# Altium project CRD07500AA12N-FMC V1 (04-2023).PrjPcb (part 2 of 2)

## Sheet 05 - Sense.SchDoc: Sense - 7.5kW WolfPACK FM3 Six-Pack Motor Drive
size 431 x 279 mm; Date: 04/2023; DocumentNumber: CRD07500AA12N-FMC; Revision: 1; SheetNumber: 5; SheetTotal: 6; SheetSize: B
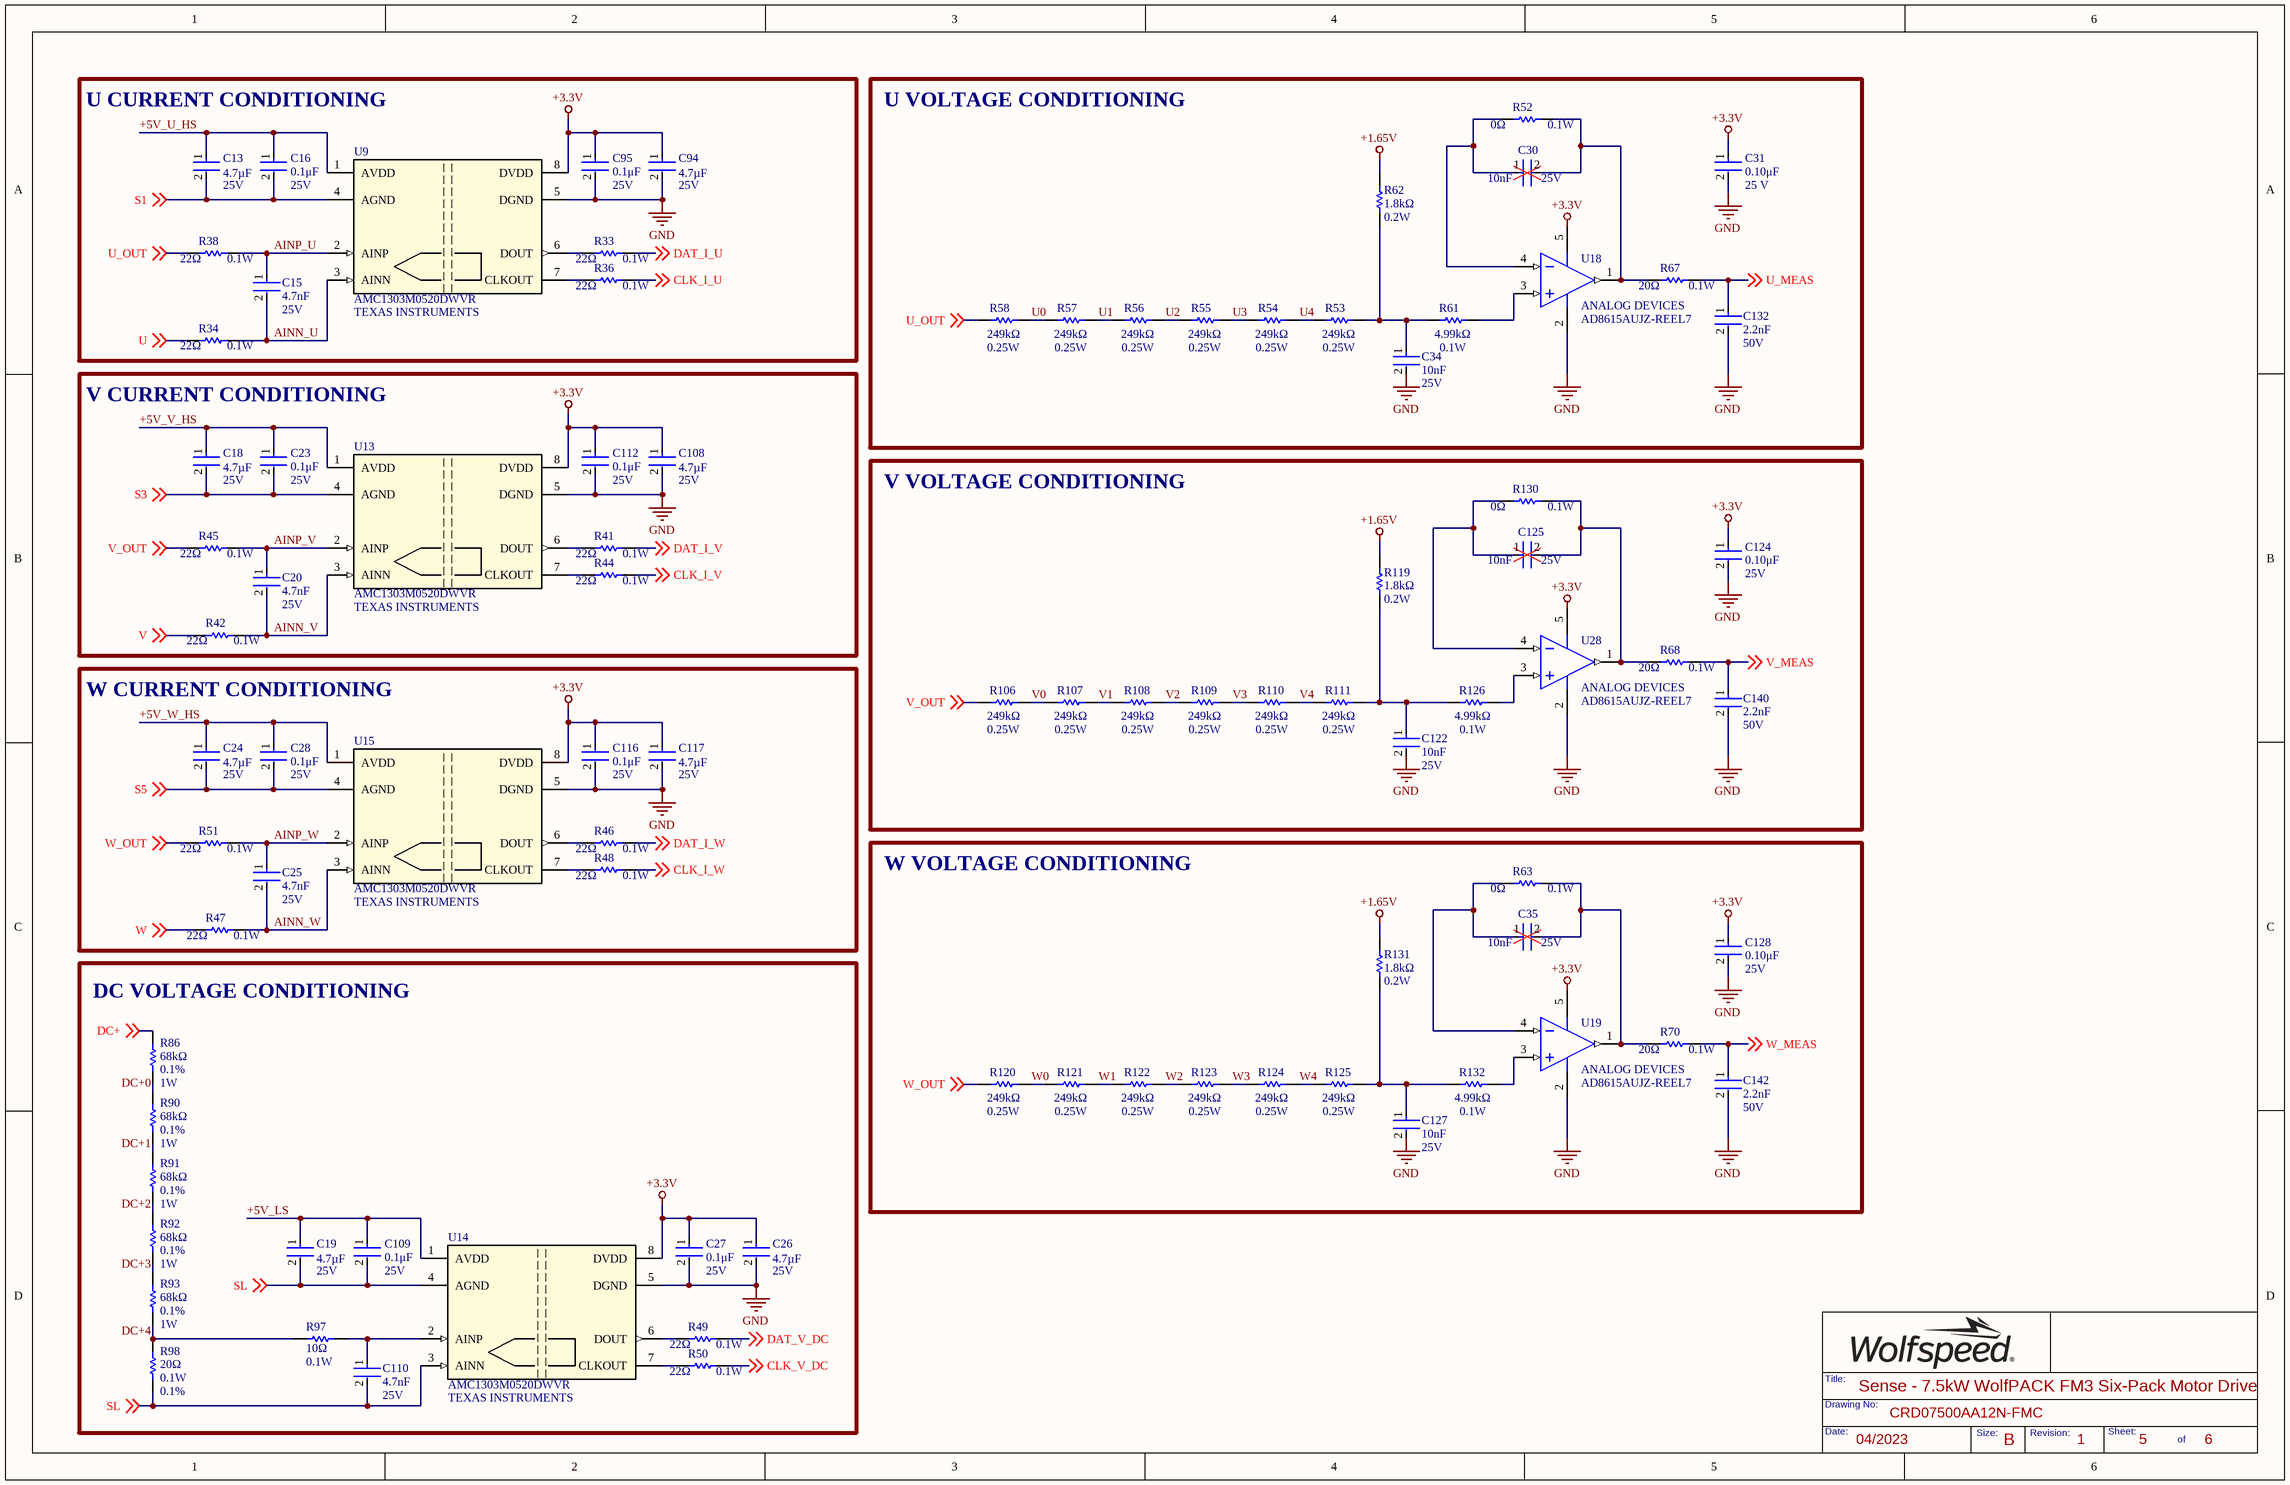
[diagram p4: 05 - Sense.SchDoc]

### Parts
C13  Capacitance: 4.7µF  Voltage Rating: 25V  [FP-C0603C-CF-IPC_B]  (hidden comment: CL10A475MA8NQNC)
C15  Capacitance: 4.7nF  Voltage Rating: 25V  [FP-C0603C-CF-IPC_B]  (hidden comment: C0603C472K3RAC7867)
C16  Voltage Rating: 25V  Capacitance: 0.1μF  [FP-C0603C-CF-IPC_B]  (hidden comment: C0603C104K3RACTU)
C18  Capacitance: 4.7µF  Voltage Rating: 25V  [FP-C0603C-CF-IPC_B]  (hidden comment: CL10A475MA8NQNC)
C19  Capacitance: 4.7µF  Voltage Rating: 25V  [FP-C0603C-CF-IPC_B]  (hidden comment: CL10A475MA8NQNC)
C20  Capacitance: 4.7nF  Voltage Rating: 25V  [FP-C0603C-CF-IPC_B]  (hidden comment: C0603C472K3RAC7867)
C23  Voltage Rating: 25V  Capacitance: 0.1μF  [FP-C0603C-CF-IPC_B]  (hidden comment: C0603C104K3RACTU)
C24  Capacitance: 4.7µF  Voltage Rating: 25V  [FP-C0603C-CF-IPC_B]  (hidden comment: CL10A475MA8NQNC)
C25  Capacitance: 4.7nF  Voltage Rating: 25V  [FP-C0603C-CF-IPC_B]  (hidden comment: C0603C472K3RAC7867)
C26  Capacitance: 4.7µF  Voltage Rating: 25V  [FP-C0603C-CF-IPC_B]  (hidden comment: CL10A475MA8NQNC)
C27  Voltage Rating: 25V  Capacitance: 0.1μF  [FP-C0603C-CF-IPC_B]  (hidden comment: C0603C104K3RACTU)
C28  Voltage Rating: 25V  Capacitance: 0.1μF  [FP-C0603C-CF-IPC_B]  (hidden comment: C0603C104K3RACTU)
C30  value 10nF  Voltage Rating: 25V  [FP-C0603C-CF-IPC_B]  (hidden comment: CL10B103KA8WPNC)
C31  Voltage Rating: 25 V  Capacitance: 0.10μF  [FP-C0603C-CF-IPC_B]  (hidden comment: C0603C104K3RACTU)
C34  value 10nF  Voltage Rating: 25V  [FP-C0603C-CF-IPC_B]  (hidden comment: CL10B103KA8WPNC)
C35  value 10nF  Voltage Rating: 25V  [FP-C0603C-CF-IPC_B]  (hidden comment: CL10B103KA8WPNC)
C94  Capacitance: 4.7µF  Voltage Rating: 25V  [FP-C0603C-CF-IPC_B]  (hidden comment: CL10A475MA8NQNC)
C95  Voltage Rating: 25V  Capacitance: 0.1μF  [FP-C0603C-CF-IPC_B]  (hidden comment: C0603C104K3RACTU)
C108  Capacitance: 4.7µF  Voltage Rating: 25V  [FP-C0603C-CF-IPC_B]  (hidden comment: CL10A475MA8NQNC)
C109  Voltage Rating: 25V  Capacitance: 0.1μF  [FP-C0603C-CF-IPC_B]  (hidden comment: C0603C104K3RACTU)
C110  Capacitance: 4.7nF  Voltage Rating: 25V  [FP-C0603C-CF-IPC_B]  (hidden comment: C0603C472K3RAC7867)
C112  Voltage Rating: 25V  Capacitance: 0.1μF  [FP-C0603C-CF-IPC_B]  (hidden comment: C0603C104K3RACTU)
C116  Voltage Rating: 25V  Capacitance: 0.1μF  [FP-C0603C-CF-IPC_B]  (hidden comment: C0603C104K3RACTU)
C117  Capacitance: 4.7µF  Voltage Rating: 25V  [FP-C0603C-CF-IPC_B]  (hidden comment: CL10A475MA8NQNC)
C122  value 10nF  Voltage Rating: 25V  [FP-C0603C-CF-IPC_B]  (hidden comment: CL10B103KA8WPNC)
C124  Voltage Rating: 25V  Capacitance: 0.10μF  [FP-C0603C-CF-IPC_B]  (hidden comment: C0603C104K3RACTU)
C125  value 10nF  Voltage Rating: 25V  [FP-C0603C-CF-IPC_B]  (hidden comment: CL10B103KA8WPNC)
C127  value 10nF  Voltage Rating: 25V  [FP-C0603C-CF-IPC_B]  (hidden comment: CL10B103KA8WPNC)
C128  Voltage Rating: 25V  Capacitance: 0.10μF  [FP-C0603C-CF-IPC_B]  (hidden comment: C0603C104K3RACTU)
C132  Capacitance: 2.2nF  Voltage Rating: 50V  [FP-GCM188-0_1-IPC_A]  (hidden comment: CGA3E2X7R1H222K080AA)
C140  Capacitance: 2.2nF  Voltage Rating: 50V  [FP-GCM188-0_1-IPC_A]  (hidden comment: CGA3E2X7R1H222K080AA)
C142  Capacitance: 2.2nF  Voltage Rating: 50V  [FP-GCM188-0_1-IPC_A]  (hidden comment: CGA3E2X7R1H222K080AA)
R33  Resistance: 22Ω  Power Rating: 0.1W  [FP-MCR03-IPC_B]  (hidden comment: RC0603FR-1322RL)
R34  Resistance: 22Ω  Power Rating: 0.1W  [FP-MCR03-IPC_B]  (hidden comment: RC0603FR-1322RL)
R36  Resistance: 22Ω  Power Rating: 0.1W  [FP-MCR03-IPC_B]  (hidden comment: RC0603FR-1322RL)
R38  Resistance: 22Ω  Power Rating: 0.1W  [FP-MCR03-IPC_B]  (hidden comment: RC0603FR-1322RL)
R41  Resistance: 22Ω  Power Rating: 0.1W  [FP-MCR03-IPC_B]  (hidden comment: RC0603FR-1322RL)
R42  Resistance: 22Ω  Power Rating: 0.1W  [FP-MCR03-IPC_B]  (hidden comment: RC0603FR-1322RL)
R44  Resistance: 22Ω  Power Rating: 0.1W  [FP-MCR03-IPC_B]  (hidden comment: RC0603FR-1322RL)
R45  Resistance: 22Ω  Power Rating: 0.1W  [FP-MCR03-IPC_B]  (hidden comment: RC0603FR-1322RL)
R46  Resistance: 22Ω  Power Rating: 0.1W  [FP-MCR03-IPC_B]  (hidden comment: RC0603FR-1322RL)
R47  Resistance: 22Ω  Power Rating: 0.1W  [FP-MCR03-IPC_B]  (hidden comment: RC0603FR-1322RL)
R48  Resistance: 22Ω  Power Rating: 0.1W  [FP-MCR03-IPC_B]  (hidden comment: RC0603FR-1322RL)
R49  Resistance: 22Ω  Power Rating: 0.1W  [FP-MCR03-IPC_B]  (hidden comment: RC0603FR-1322RL)
R50  Resistance: 22Ω  Power Rating: 0.1W  [FP-MCR03-IPC_B]  (hidden comment: RC0603FR-1322RL)
R51  Resistance: 22Ω  Power Rating: 0.1W  [FP-MCR03-IPC_B]  (hidden comment: RC0603FR-1322RL)
R52  Resistance: 0Ω  Power Rating: 0.1W  [FP-MCR03-IPC_B]  (hidden comment: RC0603FR-070RL)
R53  Resistance: 249kΩ  Power: 0.25W  [RESC3216X65X50NL15T25]  (hidden comment: TNPW1206249KBEEA)
R54  Resistance: 249kΩ  Power: 0.25W  [RESC3216X65X50NL15T25]  (hidden comment: TNPW1206249KBEEA)
R55  Resistance: 249kΩ  Power: 0.25W  [RESC3216X65X50NL15T25]  (hidden comment: TNPW1206249KBEEA)
R56  Resistance: 249kΩ  Power: 0.25W  [RESC3216X65X50NL15T25]  (hidden comment: TNPW1206249KBEEA)
R57  Resistance: 249kΩ  Power: 0.25W  [RESC3216X65X50NL15T25]  (hidden comment: TNPW1206249KBEEA)
R58  Resistance: 249kΩ  Power: 0.25W  [RESC3216X65X50NL15T25]  (hidden comment: TNPW1206249KBEEA)
R61  Power Rating: 0.1W  Resistance: 4.99kΩ  [FP-MCR03-IPC_B]  (hidden comment: RC0603FR-074K99L)
R62  Resistance: 1.8kΩ  Max Power Dissipation: 0.2W  [FP-MCR03-IPC_B]  (hidden comment: ERJ-PB3B1801V)
R63  Resistance: 0Ω  Power Rating: 0.1W  [FP-MCR03-IPC_B]  (hidden comment: RC0603FR-070RL)
R67  Resistance: 20Ω  Power Rating: 0.1W  [FP-MCR03-IPC_B]  (hidden comment: RT0603BRD0720RL)
R68  Resistance: 20Ω  Power Rating: 0.1W  [FP-MCR03-IPC_B]  (hidden comment: RT0603BRD0720RL)
R70  Resistance: 20Ω  Power Rating: 0.1W  [FP-MCR03-IPC_B]  (hidden comment: RT0603BRD0720RL)
R86  Resistance: 68kΩ  Power: 1W  Tolerance: 0.1%  [RESC3216X65X50NL15T25]  (hidden comment: PHPA1206E6802BST1)
R90  Resistance: 68kΩ  Power: 1W  Tolerance: 0.1%  [RESC3216X65X50NL15T25]  (hidden comment: PHPA1206E6802BST1)
R91  Resistance: 68kΩ  Power: 1W  Tolerance: 0.1%  [RESC3216X65X50NL15T25]  (hidden comment: PHPA1206E6802BST1)
R92  Resistance: 68kΩ  Power: 1W  Tolerance: 0.1%  [RESC3216X65X50NL15T25]  (hidden comment: PHPA1206E6802BST1)
R93  Resistance: 68kΩ  Power: 1W  Tolerance: 0.1%  [RESC3216X65X50NL15T25]  (hidden comment: PHPA1206E6802BST1)
R97  Resistance: 10Ω  Max Power Dissipation: 0.1W  [FP-MCR03-IPC_B]  (hidden comment: RC0603JR-0710RL)
R98  Tolerance: 0.1%  Resistance: 20Ω  Power Rating: 0.1W  [FP-MCR03-IPC_B]  (hidden comment: RT0603BRD0720RL)
R106  Resistance: 249kΩ  Power: 0.25W  [RESC3216X65X50NL15T25]  (hidden comment: TNPW1206249KBEEA)
R107  Resistance: 249kΩ  Power: 0.25W  [RESC3216X65X50NL15T25]  (hidden comment: TNPW1206249KBEEA)
R108  Resistance: 249kΩ  Power: 0.25W  [RESC3216X65X50NL15T25]  (hidden comment: TNPW1206249KBEEA)
R109  Resistance: 249kΩ  Power: 0.25W  [RESC3216X65X50NL15T25]  (hidden comment: TNPW1206249KBEEA)
R110  Resistance: 249kΩ  Power: 0.25W  [RESC3216X65X50NL15T25]  (hidden comment: TNPW1206249KBEEA)
R111  Resistance: 249kΩ  Power: 0.25W  [RESC3216X65X50NL15T25]  (hidden comment: TNPW1206249KBEEA)
R119  Resistance: 1.8kΩ  Max Power Dissipation: 0.2W  [FP-MCR03-IPC_B]  (hidden comment: ERJ-PB3B1801V)
R120  Resistance: 249kΩ  Power: 0.25W  [RESC3216X65X50NL15T25]  (hidden comment: TNPW1206249KBEEA)
R121  Resistance: 249kΩ  Power: 0.25W  [RESC3216X65X50NL15T25]  (hidden comment: TNPW1206249KBEEA)
R122  Resistance: 249kΩ  Power: 0.25W  [RESC3216X65X50NL15T25]  (hidden comment: TNPW1206249KBEEA)
R123  Resistance: 249kΩ  Power: 0.25W  [RESC3216X65X50NL15T25]  (hidden comment: TNPW1206249KBEEA)
R124  Resistance: 249kΩ  Power: 0.25W  [RESC3216X65X50NL15T25]  (hidden comment: TNPW1206249KBEEA)
R125  Resistance: 249kΩ  Power: 0.25W  [RESC3216X65X50NL15T25]  (hidden comment: TNPW1206249KBEEA)
R126  Power Rating: 0.1W  Resistance: 4.99kΩ  [FP-MCR03-IPC_B]  (hidden comment: RC0603FR-074K99L)
R130  Resistance: 0Ω  Power Rating: 0.1W  [FP-MCR03-IPC_B]  (hidden comment: RC0603FR-070RL)
R131  Resistance: 1.8kΩ  Max Power Dissipation: 0.2W  [FP-MCR03-IPC_B]  (hidden comment: ERJ-PB3B1801V)
R132  Power Rating: 0.1W  Resistance: 4.99kΩ  [FP-MCR03-IPC_B]  (hidden comment: RC0603FR-074K99L)
U9  AMC1303M0520DWVR  Manufacturer: TEXAS INSTRUMENTS  [DWV0008A]
U13  AMC1303M0520DWVR  Manufacturer: TEXAS INSTRUMENTS  [DWV0008A]
U14  AMC1303M0520DWVR  Manufacturer: TEXAS INSTRUMENTS  [DWV0008A]
U15  AMC1303M0520DWVR  Manufacturer: TEXAS INSTRUMENTS  [DWV0008A]
U18  Manufacturer: ANALOG DEVICES  [ADI-UJ-5_M]  (hidden comment: AD8615AUJZ-REEL7)
U19  Manufacturer: ANALOG DEVICES  [ADI-UJ-5_M]  (hidden comment: AD8615AUJZ-REEL7)
U28  Manufacturer: ANALOG DEVICES  [ADI-UJ-5_M]  (hidden comment: AD8615AUJZ-REEL7)

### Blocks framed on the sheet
U CURRENT CONDITIONING: C13 C15 C16 C94 C95 R33 R34 R36 R38 U9
U VOLTAGE CONDITIONING: C30 C31 C34 C132 R52-R58 R61 R62 R67 U18
V CURRENT CONDITIONING: C18 C20 C23 C108 C112 R41 R42 R44 R45 U13
V VOLTAGE CONDITIONING: C122 C124 C125 C140 R68 R106-R111 R119 R126 R130 U28
W CURRENT CONDITIONING: C24 C25 C28 C116 C117 R46-R48 R51 U15
W VOLTAGE CONDITIONING: C35 C127 C128 C142 R63 R70 R120-R125 R131 R132 U19
DC VOLTAGE CONDITIONING: C19 C26 C27 C109 C110 R49 R50 R86 R90-R93 R97 R98 U14

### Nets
+1.65V: R62.2 R119.2 R131.2
+3.3V: C26.1 C27.1 C31.1 C94.1 C95.1 C108.1 C112.1 C116.1 C117.1 C124.1 C128.1 U9.8(DVDD) U13.8(DVDD) U14.8(DVDD) U15.8(DVDD) U18.5(+V) U19.5(+V) U28.5(+V)
GND: C26.2 C27.2 C31.2 C34.2 C94.2 C95.2 C108.2 C112.2 C116.2 C117.2 C122.2 C124.2 C127.2 C128.2 C132.2 C140.2 C142.2 U9.5(DGND) U13.5(DGND) U14.5(DGND) U15.5(DGND) U18.2(-V) U19.2(-V) U28.2(-V)
+5V_LS: C19.1 C109.1 U14.1(AVDD)
+5V_U_HS: C13.1 C16.1 U9.1(AVDD)
+5V_V_HS: C18.1 C23.1 U13.1(AVDD)
+5V_W_HS: C24.1 C28.1 U15.1(AVDD)
AINN_U: C15.2 R34.2 U9.3(AINN)
AINN_V: C20.2 R42.2 U13.3(AINN)
AINN_W: C25.2 R47.2 U15.3(AINN)
AINP_U: C15.1 R38.2 U9.2(AINP)
AINP_V: C20.1 R45.2 U13.2(AINP)
AINP_W: C25.1 R51.2 U15.2(AINP)
CLK_I_U: R36.2 ; off-sheet CLK_I_U
CLK_I_V: R44.2 ; off-sheet CLK_I_V
CLK_I_W: R48.2 ; off-sheet CLK_I_W
CLK_V_DC: R50.2 ; off-sheet CLK_V_DC
DAT_I_U: R33.2 ; off-sheet DAT_I_U
DAT_I_V: R41.2 ; off-sheet DAT_I_V
DAT_I_W: R46.2 ; off-sheet DAT_I_W
DAT_V_DC: R49.2 ; off-sheet DAT_V_DC
DC+: R86.2 ; off-sheet DC+
DC+0: R86.1 R90.2
DC+1: R90.1 R91.2
DC+2: R91.1 R92.2
DC+3: R92.1 R93.2
DC+4: R93.1 R97.2 R98.2
S1: C13.2 C16.2 U9.4(AGND) ; off-sheet S1
S3: C18.2 C23.2 U13.4(AGND) ; off-sheet S3
S5: C24.2 C28.2 U15.4(AGND) ; off-sheet S5
SL: C19.2 C109.2 C110.2 R98.1 U14.3(AINN) U14.4(AGND) ; off-sheet SL
U: R34.1 ; off-sheet U
U0: R57.1 R58.2
U1: R56.1 R57.2
U2: R55.1 R56.2
U3: R54.1 R55.2
U4: R53.1 R54.2
U_MEAS: C132.1 R67.2 ; off-sheet U_MEAS
U_OUT: R38.1 R58.1 ; off-sheet U_OUT
V: R42.1 ; off-sheet V
V0: R106.2 R107.1
V1: R107.2 R108.1
V2: R108.2 R109.1
V3: R109.2 R110.1
V4: R110.2 R111.1
V_MEAS: C140.1 R68.2 ; off-sheet V_MEAS
V_OUT: R45.1 R106.1 ; off-sheet V_OUT
W: R47.1 ; off-sheet W
W0: R120.2 R121.1
W1: R121.2 R122.1
W2: R122.2 R123.1
W3: R123.2 R124.1
W4: R124.2 R125.1
W_MEAS: C142.1 R70.2 ; off-sheet W_MEAS
W_OUT: R51.1 R120.1 ; off-sheet W_OUT
NetC30_1: C30.1 R52.2 U18.4(-IN)
NetC30_2: C30.2 R52.1 R67.1 U18.1(OUT)
NetC34_1: C34.1 R53.2 R61.1 R62.1
NetC35_1: C35.1 R63.2 U19.4(-IN)
NetC35_2: C35.2 R63.1 R70.1 U19.1(OUT)
NetC110_1: C110.1 R97.1 U14.2(AINP)
NetC122_1: C122.1 R111.2 R119.1 R126.1
NetC125_1: C125.1 R130.2 U28.4(-IN)
NetC125_2: C125.2 R68.1 R130.1 U28.1(OUT)
NetC127_1: C127.1 R125.2 R131.1 R132.1
NetR33_1: R33.1 U9.6(DOUT)
NetR36_1: R36.1 U9.7(CLKOUT)
NetR41_1: R41.1 U13.6(DOUT)
NetR44_1: R44.1 U13.7(CLKOUT)
NetR46_1: R46.1 U15.6(DOUT)
NetR48_1: R48.1 U15.7(CLKOUT)
NetR49_1: R49.1 U14.6(DOUT)
NetR50_1: R50.1 U14.7(CLKOUT)
NetR61_2: R61.2 U18.3(+IN)
NetR126_2: R126.2 U28.3(+IN)
NetR132_2: R132.2 U19.3(+IN)

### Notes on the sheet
- Labels drawn without touching a wire or pin: ~{}

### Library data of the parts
C13 C18 C19 C24 C26 C94 C108 C117 = CL10A475MA8NQNC: CAP CER 4.7UF 25V X5R 0603; Manufacturer: SAMSUNG; Tolerance: 20%; Value: 4.7µF
C15 C20 C25 C110 = C0603C472K3RAC7867: CAP CER 4700PF 25V 10% X7R 0603; Manufacturer: KEMET; Manufacturer Part Number: C0603C472K3RACTU; Dielectric Material: Ceramic; Value: 4.7nF
C16 C23 C27 C28 C31 C95 C109 C112 C116 C124 C128 = CMP-2006-03057-2: CAP CER 0.1UF 25V X7R 0603; Manufacturer: KEMET; Value: 0.10μF; Material: Ceramic; Tolerance: 0.1; Temperature Coefficient: 30ppm/°C; Automotive Grade: Grade 1
C30 C34 C35 C122 C125 C127 = CL10B103KA8WPNC: CAP CER 10000PF 25V X7R 0603; Manufacturer: SAMSUNG; Tolerance: 10%
C132 C140 C142 = CGA3E2X7R1H222K080AA: CAP CER 2200PF 50V X7R 0603; Manufacturer: TDK; Tolerance: 10%; Value: 2.2nF
R33 R34 R36 R38 R41 R42 R44-R51 = RC0603FR-1322RL: RES 22 OHM 1% 1/10W 0603; Manufacturer: YAGEO; Temperature Coefficient: 100ppm/°C; Voltage Rating: 50V; Value: 22Ω
R52 R63 R130 = RC0603FR-070RL: RES 0 OHM JUMPER 1/10W 0603; Manufacturer: YAGEO; Tolerance: 1%; Voltage Rating (DC): 50V; Max Power Dissipation: 100mW; Temperature Coefficient: 200ppm/°C; Current Rating: 1A; Working Voltage: 75V; Value: 0Ω
R53 R111 R125 = CMP-2003-04604-1: RES 249K OHM 0.1% 1/4W 1206; Manufacturer: VISHAY DALE; Value: 249kΩ
R54-R58 R106-R110 R120-R124 = CMP-2003-04604-1: RES 249K OHM 0.1% 1/4W 1206; Manufacturer: VISHAY; Value: 249kΩ
R61 R126 R132 = RC0603FR-074K99L: RES 4.99K OHM 1% 1/10W 0603; Manufacturer: YAGEO; Voltage Rating: 75V; Temperature Coefficient: 100ppm/°C; Voltage Rating (DC): 50V; Value: 4.99kΩ
R62 R119 R131 = ERJ-PB3B1801V: RES SMD 1.8K OHM 0.1% 1/5W 0603; Manufacturer: PANASONIC; Temperature Coefficient: 50ppm/°C; Value: 1.8kΩ
R67 R68 R70 R98 = RT0603BRD0720RL: RES SMD 20 OHM 0.1% 1/10W 0603; Manufacturer: YAGEO; Temperature Coefficient: 25ppm/°C; Max Power Dissipation: 100mW; Voltage Rating: 75V; Voltage Rating (DC): 50V; Value: 20Ω
R86 R90-R93 = PHPA1206E6802BST1: THIN FILM RES SMD 68K OHM 0.1% 1; Manufacturer: VISHAY; Value: 68kΩ
R97 = RC0603JR-0710RL: RES 10 OHM 5% 1/10W 0603; Manufacturer: YAGEO; Temperature Coefficient: 200ppm/°C; Power Rating: 100mW; Voltage Rating: 50V; Value: 10Ω
U9 U13-U15 = AMC1303M0520DWVR: IC ISOLATED MOD 16BIT 78K 8SOIC; Interface: Serial; Number of Inputs: 1
U18 U19 U28 = CMP-0384-02059-2: IC OPAMP GP 1 CIRCUIT TSOT23-5; Generic Part Number: AD8615; Iq/Amp: 1.7mA; V Span Max: 6V; Amplifiers Per Package: 1; Small Signal Bandwidth: 23MHz; Input Offset Voltage: 80uV; V Span Min: 2.7V; Slew Rate: 12V/us; Input Bias Current: 200fA

## Sheet 06 - Auxiliary Power.SchDoc: Auxiliary Power - 7.5kW WolfPACK 6-Pack M. Drive
size 431 x 279 mm; Date: 04/2023; DocumentNumber: CRD07500AA12N-FMC; Revision: 1; SheetNumber: 6; SheetTotal: 6; SheetSize: B
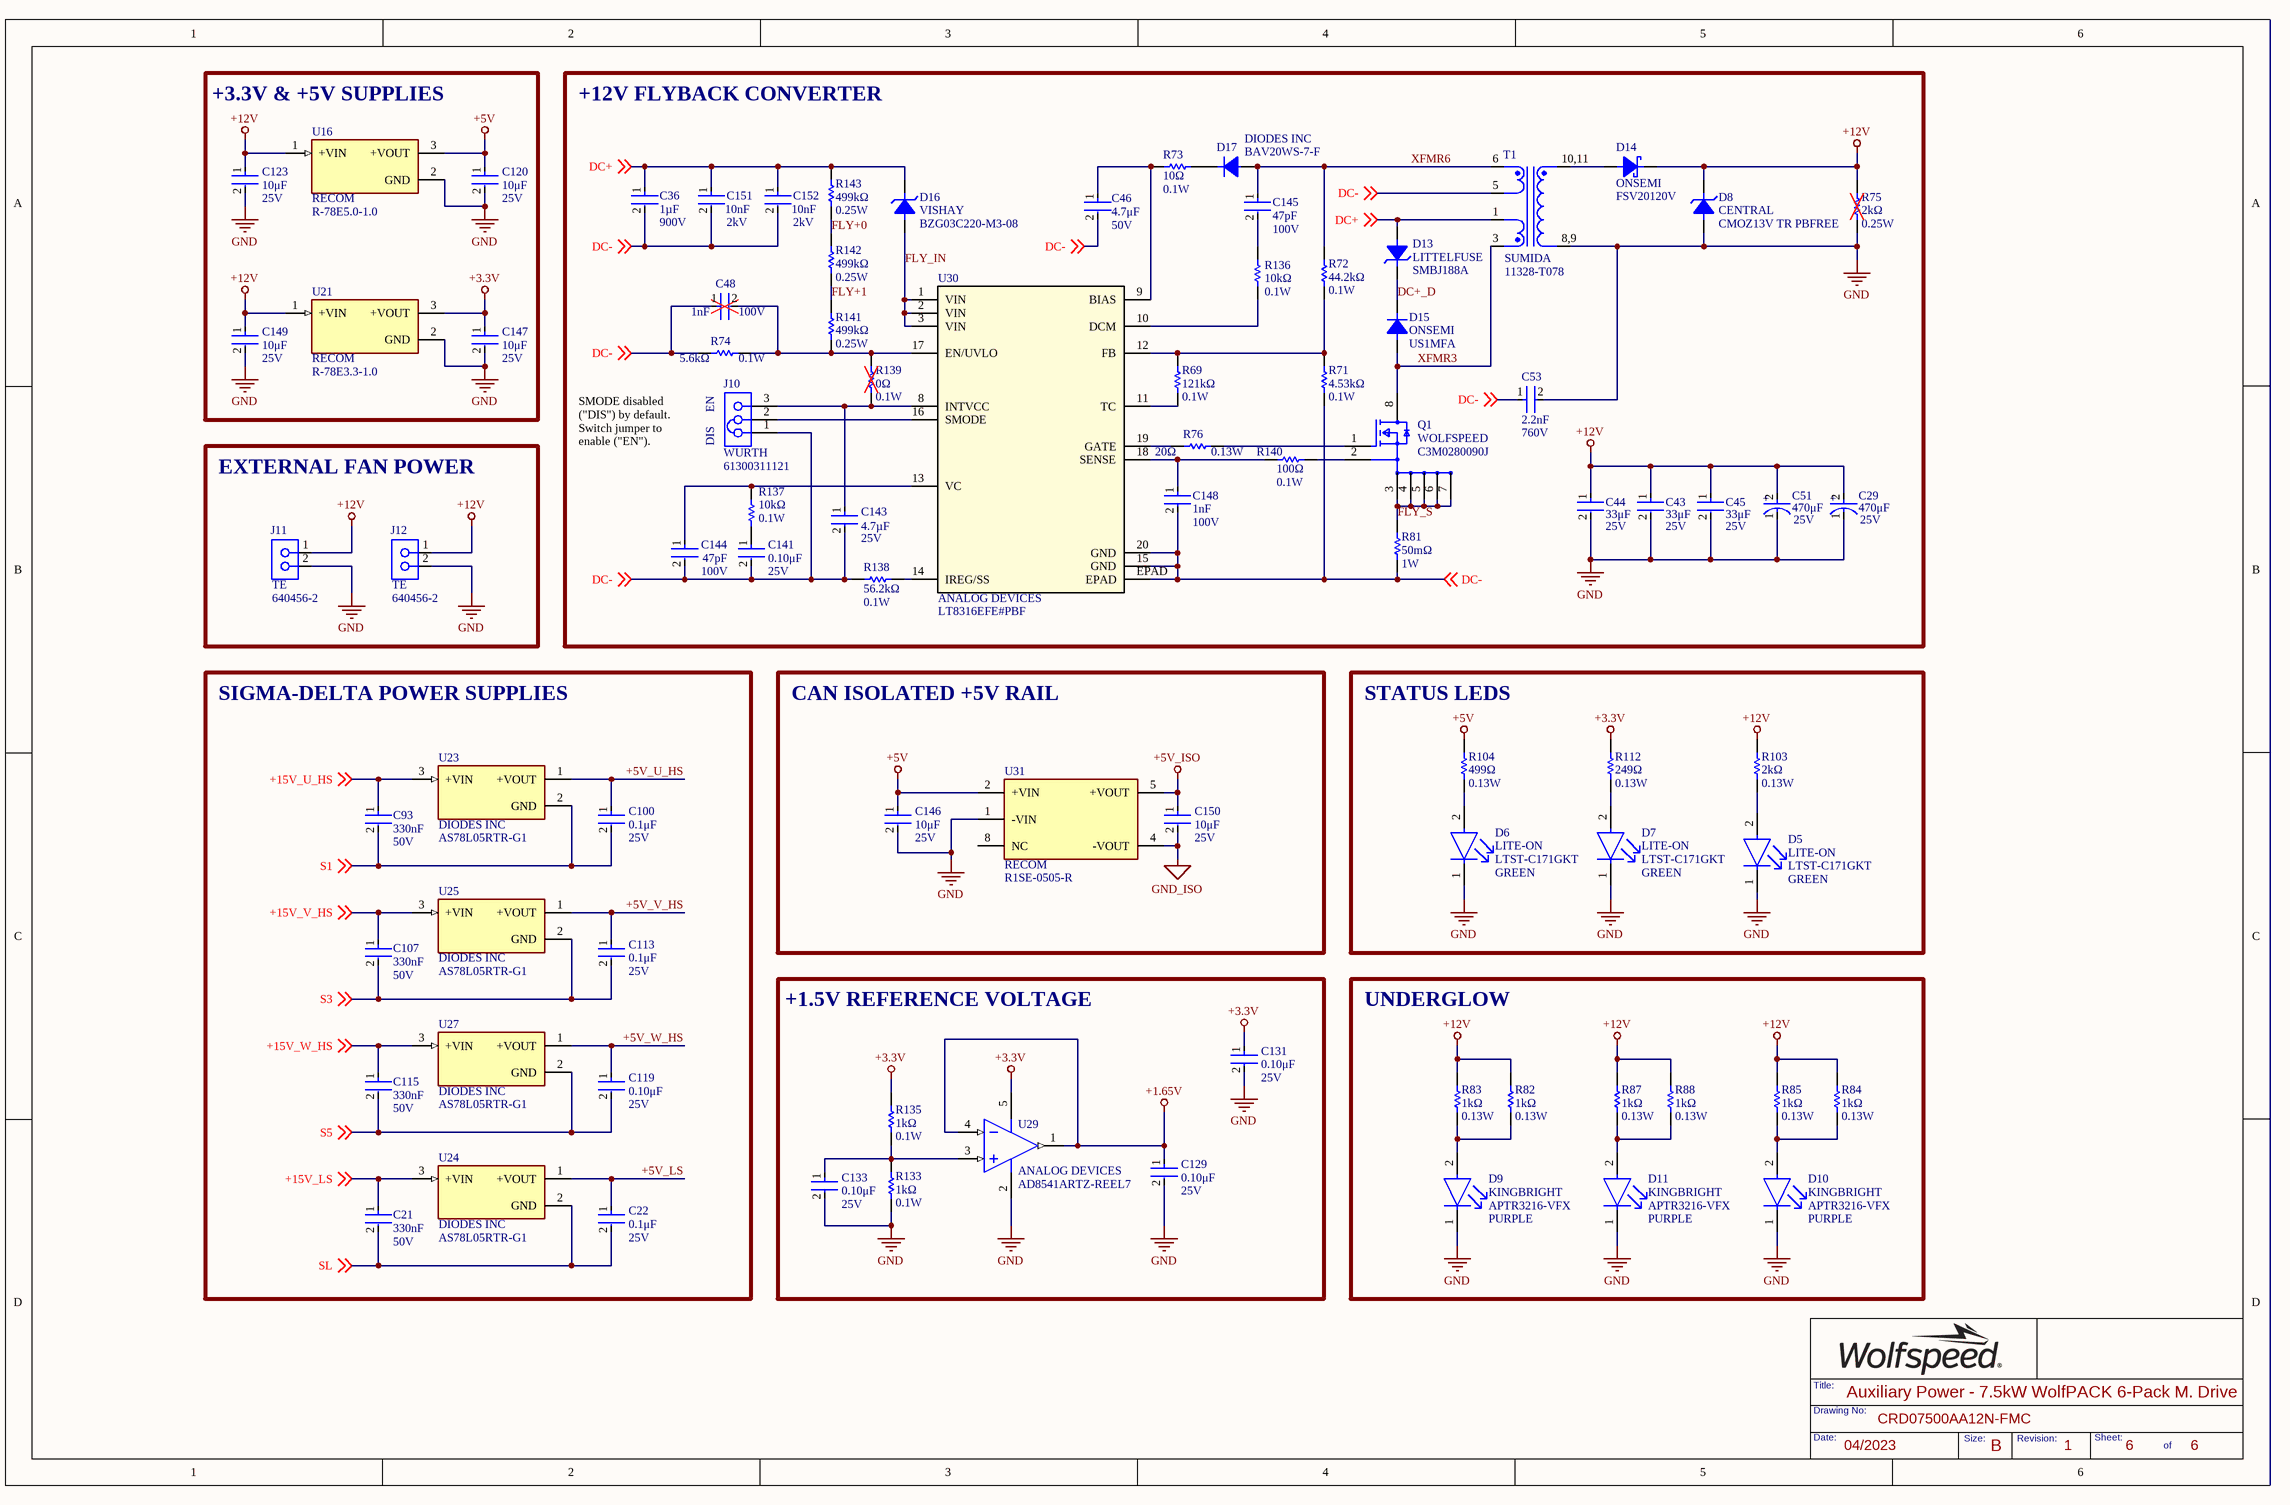
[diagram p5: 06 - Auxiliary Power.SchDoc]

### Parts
C21  Capacitance: 330nF  Voltage: 50V  [FP-C0603C-CF-IPC_B]  (hidden comment: C1608X7R1H334K080AC)
C22  Voltage Rating: 25V  Capacitance: 0.1μF  [FP-C0603C-CF-IPC_B]  (hidden comment: C0603C104K3RACTU)
C29  Voltage Rating: 25V  Capacitance: 470μF  [FP-EEH-G-MFG]  (hidden comment: EEHZK1E471P)
C36  Capacitance: 1µF  Rated Voltage (DC): 900V  [WCAP-FTDB_L32W9H18]  (hidden comment: 890724427001CS)
C43  Voltage Rating (DC): 25V  Capacitance: 33μF  [FP-C3216-160-0_2-IPC_C]  (hidden comment: C3216JB1E336M160AC)
C44  Voltage Rating (DC): 25V  Capacitance: 33μF  [FP-C3216-160-0_2-IPC_C]  (hidden comment: C3216JB1E336M160AC)
C45  Voltage Rating (DC): 25V  Capacitance: 33μF  [FP-C3216-160-0_2-IPC_C]  (hidden comment: C3216JB1E336M160AC)
C46  Voltage Rating: 50V  Capacitance: 4.7μF  [FP-CL21-IPC_C]  (hidden comment: CL21A475KBQNNNE)
C48  Capacitance: 1nF  Voltage Rating: 100V  [FP-C0603C-CF-IPC_B]  (hidden comment: C0603C102J1GACTU)
C51  Voltage Rating: 25V  Capacitance: 470μF  [FP-EEH-G-MFG]  (hidden comment: EEHZK1E471P)
C53  Capacitance: 2.2nF  Voltage Rating (AC): 760V  [FP-VY1470-MFG]  (hidden comment: VY1222M47Y5UQ6TV0)
C93  Capacitance: 330nF  Voltage: 50V  [FP-C0603C-CF-IPC_B]  (hidden comment: C1608X7R1H334K080AC)
C100  Voltage Rating: 25V  Capacitance: 0.1μF  [FP-C0603C-CF-IPC_B]  (hidden comment: C0603C104K3RACTU)
C107  Capacitance: 330nF  Voltage: 50V  [FP-C0603C-CF-IPC_B]  (hidden comment: C1608X7R1H334K080AC)
C113  Voltage Rating: 25V  Capacitance: 0.1μF  [FP-C0603C-CF-IPC_B]  (hidden comment: C0603C104K3RACTU)
C115  Capacitance: 330nF  Voltage: 50V  [FP-C0603C-CF-IPC_B]  (hidden comment: C1608X7R1H334K080AC)
C119  Voltage Rating: 25V  Capacitance: 0.10μF  [FP-C0603C-CF-IPC_B]  (hidden comment: C0603C104K3RACTU)
C120  Voltage Rating: 25V  Capacitance: 10μF  [FP-CL31-IPC_B]  (hidden comment: CL31B106KAHSFNE)
C123  Voltage Rating: 25V  Capacitance: 10μF  [FP-CL31-IPC_B]  (hidden comment: CL31B106KAHSFNE)
C129  Voltage Rating: 25V  Capacitance: 0.10μF  [FP-C0603C-CF-IPC_B]  (hidden comment: C0603C104K3RACTU)
C131  Voltage Rating: 25V  Capacitance: 0.10μF  [FP-C0603C-CF-IPC_B]  (hidden comment: C0603C104K3RACTU)
C133  Voltage Rating: 25V  Capacitance: 0.10μF  [FP-C0603C-CF-IPC_B]  (hidden comment: C0603C104K3RACTU)
C141  Voltage Rating: 25V  Capacitance: 0.10μF  [FP-C0603C-CF-IPC_B]  (hidden comment: C0603C104K3RACTU)
C143  Capacitance: 4.7µF  Voltage Rating: 25V  [FP-C0603C-CF-IPC_B]  (hidden comment: CL10A475MA8NQNC)
C144  Capacitance: 47pF  Voltage Rating: 100V  [FP-C0603C-CF-MFG]  (hidden comment: C0603C470K1GACTU)
C145  Capacitance: 47pF  Voltage Rating: 100V  [FP-C0603C-CF-MFG]  (hidden comment: C0603C470K1GACTU)
C146  Voltage Rating: 25V  Capacitance: 10μF  [FP-CL31-IPC_B]  (hidden comment: CL31B106KAHSFNE)
C147  Voltage Rating: 25V  Capacitance: 10μF  [FP-CL31-IPC_B]  (hidden comment: CL31B106KAHSFNE)
C148  Capacitance: 1nF  Voltage Rating: 100V  [FP-C0603C-CF-IPC_B]  (hidden comment: C0603C102J1GACTU)
C149  Voltage Rating: 25V  Capacitance: 10μF  [FP-CL31-IPC_B]  (hidden comment: CL31B106KAHSFNE)
C150  Voltage Rating: 25V  Capacitance: 10μF  [FP-CL31-IPC_B]  (hidden comment: CL31B106KAHSFNE)
C151  Voltage Rating: 2kV  Capacitance: 10nF  [FP-C5750-250-0_4-IPC_A]  (hidden comment: C5750X7S3D103K250KA)
C152  Voltage Rating: 2kV  Capacitance: 10nF  [FP-C5750-250-0_4-IPC_A]  (hidden comment: C5750X7S3D103K250KA)
D5  value GREEN  Manufacturer: LITE-ON  [FP-LTST-C171GKT-MFG]  (hidden comment: LTST-C171GKT)
D6  value GREEN  Manufacturer: LITE-ON  [FP-LTST-C171GKT-MFG]  (hidden comment: LTST-C171GKT)
D7  value GREEN  Manufacturer: LITE-ON  [FP-LTST-C171GKT-MFG]  (hidden comment: LTST-C171GKT)
D8  Manufacturer: CENTRAL  [DIODE_SOD-523_1P2XP8_CNS]  (hidden comment: CMOZ13V TR PBFREE)
D9  Manufacturer Print: KINGBRIGHT  Color: PURPLE  [FP-APTR3216SECK-MFG]  (hidden comment: APTR3216-VFX)
D10  Manufacturer Print: KINGBRIGHT  Color: PURPLE  [FP-APTR3216SECK-MFG]  (hidden comment: APTR3216-VFX)
D11  Manufacturer Print: KINGBRIGHT  Color: PURPLE  [FP-APTR3216SECK-MFG]  (hidden comment: APTR3216-VFX)
D13  Manufacturer: LITTELFUSE  [SMBJSeries_LTF]  (hidden comment: SMBJ188A)
D14  Manufacturer: ONSEMI  [SOT_20100V_ONS]  (hidden comment: FSV20120V)
D15  Manufacturer: ONSEMI  [FP-425AB-MFG]  (hidden comment: US1MFA)
D16  Manufacturer: VISHAY  [FP-SMA-MFG]  (hidden comment: BZG03C220-M3-08)
D17  Manufacturer: DIODES INC  [SOD323_DIO]  (hidden comment: BAV20WS-7-F)
J10  Manufacturer: WURTH  [61300311121]  (hidden comment: 61300311121)
J11  640456-2  Manufacturer Print: TE  [TECO-640456-2_V]
J12  640456-2  Manufacturer Print: TE  [TECO-640456-2_V]
Q1  Manufacturer: WOLFSPEED  [FP-TO-263-7-MFG]  (hidden comment: C3M0280090J)
R69  Resistance: 121kΩ  Power Rating: 0.1W  [FP-MCR03-IPC_B]  (hidden comment: RT0603FRE07121KL)
R71  Resistance: 4.53kΩ  Power Rating: 0.1W  [FP-MCR03-IPC_B]  (hidden comment: RC0603FR-074K53L)
R72  Resistance: 44.2kΩ  Max Power Dissipation: 0.1W  [FP-MCR03-IPC_B]  (hidden comment: RT0603BRD0744K2L)
R73  Resistance: 10Ω  Max Power Dissipation: 0.1W  [FP-MCR03-IPC_B]  (hidden comment: RC0603JR-0710RL)
R74  Resistance: 5.6kΩ  Power Rating: 0.1W  [FP-MCR03-IPC_B]  (hidden comment: RC0603FR-135K6L)
R75  Resistance: 2kΩ  Max Power Dissipation: 0.25W  [FP-CSR1206-IPC_A]  (hidden comment: RT1206FRE072KL)
R76  Resistance: 20Ω  Max Power Dissipation: 0.13W  [RESC2013X60X35LL10T20]  (hidden comment: RT0805FRE0720RL)
R81  value 50mΩ  Power: 1W  [FP-CSR1206-IPC_A]  (hidden comment: WFC1206R0500FE66)
R82  Resistance: 1kΩ  Power Rating: 0.13W  [RESC2013X50X30LL20T20]  (hidden comment: CRCW08051K00JNTA)
R83  Resistance: 1kΩ  Power Rating: 0.13W  [RESC2013X50X30LL20T20]  (hidden comment: CRCW08051K00JNTA)
R84  Resistance: 1kΩ  Power Rating: 0.13W  [RESC2013X50X30LL20T20]  (hidden comment: CRCW08051K00JNTA)
R85  Resistance: 1kΩ  Power Rating: 0.13W  [RESC2013X50X30LL20T20]  (hidden comment: CRCW08051K00JNTA)
R87  Resistance: 1kΩ  Power Rating: 0.13W  [RESC2013X50X30LL20T20]  (hidden comment: CRCW08051K00JNTA)
R88  Resistance: 1kΩ  Power Rating: 0.13W  [RESC2013X50X30LL20T20]  (hidden comment: CRCW08051K00JNTA)
R103  Resistance: 2kΩ  Max Power Dissipation: 0.13W  [FP-MCR10-IPC_A]  (hidden comment: RT0805FRE072KL)
R104  Resistance: 499Ω  Max Power Dissipation: 0.13W  [FP-MCR10-IPC_A]  (hidden comment: RC0805FR-07499RL)
R112  Resistance: 249Ω  Power Rating: 0.13W  [FP-MCR10-IPC_A]  (hidden comment: RC0805FR-07249RL)
R133  Resistance: 1kΩ  Power Rating: 0.1W  [FP-MCR03-IPC_B]  (hidden comment: RT0603DRD071KL)
R135  Resistance: 1kΩ  Power Rating: 0.1W  [FP-MCR03-IPC_B]  (hidden comment: RT0603DRD071KL)
R136  Resistance: 10kΩ  Max Power Dissipation: 0.1W  [FP-MCR03-IPC_B]  (hidden comment: ERJ3EKF1002V)
R137  Resistance: 10kΩ  Max Power Dissipation: 0.1W  [FP-MCR03-IPC_B]  (hidden comment: ERJ3EKF1002V)
R138  Resistance: 56.2kΩ  Power Rating: 0.1W  [FP-MCR03-IPC_B]  (hidden comment: RT0603BRD0756K2L)
R139  Resistance: 0Ω  Power Rating: 0.1W  [FP-MCR03-IPC_B]  (hidden comment: RC0603FR-070RL)
R140  Resistance: 100Ω  Power Rating: 0.1W  [FP-MCR03-IPC_B]  (hidden comment: RT0603FRE07100RL)
R141  Resistance: 499kΩ  Max Power Dissipation: 0.25W  [FP-CSR1206-IPC_A]  (hidden comment: RT1206DRD07499KL)
R142  Resistance: 499kΩ  Max Power Dissipation: 0.25W  [FP-CSR1206-IPC_A]  (hidden comment: RT1206DRD07499KL)
R143  Resistance: 499kΩ  Max Power Dissipation: 0.25W  [FP-CSR1206-IPC_A]  (hidden comment: RT1206DRD07499KL)
T1  11328-T078  Manufacturer: SUMIDA  [11328-T078]
U16  Manufacturer: RECOM  [CONV_R-78E5.0-1.0]  (hidden comment: R-78E5.0-1.0)
U21  Manufacturer: RECOM  [CONV_R-78E3.3-1.0]  (hidden comment: R-78E3.3-1.0)
U23  Manufacturer: DIODES INC  [SOT-89_4P5X2P45_DIO]  (hidden comment: AS78L05RTR-G1)
U24  Manufacturer: DIODES INC  [SOT-89_4P5X2P45_DIO]  (hidden comment: AS78L05RTR-G1)
U25  Manufacturer: DIODES INC  [SOT-89_4P5X2P45_DIO]  (hidden comment: AS78L05RTR-G1)
U27  Manufacturer: DIODES INC  [SOT-89_4P5X2P45_DIO]  (hidden comment: AS78L05RTR-G1)
U29  AD8541ARTZ-REEL7  Manufacturer: ANALOG DEVICES  [ADI-RJ-5_N]
U30  Manufacturer: ANALOG DEVICES  [TSSOP20_FE_BB(16)]  (hidden comment: LT8316EFE#PBF)
U31  Manufacturer: RECOM  [FP-R1SE-0505-R-MFG]  (hidden comment: R1SE-0505-R)

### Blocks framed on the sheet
+3.3V & +5V SUPPLIES: C120 C123 C147 C149 U16 U21
+12V FLYBACK CONVERTER: C29 C36 C43-C46 C48 C51 C53 C141 C143-C145 C148 C151 C152 D8 D13-D17 J10 Q1 R69 R71-R76 R81 R136-R143 T1 U30
EXTERNAL FAN POWER: J11 J12
SIGMA-DELTA POWER SUPPLIES: C21 C22 C93 C100 C107 C113 C115 C119 U23-U25 U27
CAN ISOLATED +5V RAIL: C146 C150 U31
STATUS LEDS: D5-D7 R103 R104 R112
+1.5V REFERENCE VOLTAGE: C129 C131 C133 R133 R135 U29
UNDERGLOW: D9-D11 R82-R85 R87 R88

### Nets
+1.65V: C129.1 U29.1(OUT_A) U29.4(-IN_A)
+3.3V: C131.1 C147.1 R112.2 R135.2 U21.3(+VOUT) U29.5(+V)
+5V: C120.1 C146.1 R104.2 U16.3(+VOUT) U31.2(+VIN)
+5V_ISO: C150.1 U31.5(+VOUT)
+12V: C29.2(A) C43.1 C44.1 C45.1 C51.2(A) C123.1 C149.1 D8.1 D14.3 J11.1 J12.1 R75.2 R82.2 R83.2 R84.2 R85.2 R87.2 R88.2 R103.2 U16.1(+VIN) U21.1(+VIN)
GND: C29.1(C) C43.2 C44.2 C45.2 C51.1(C) C53.2 C120.2 C123.2 C129.2 C131.2 C133.2 C146.2 C147.2 C149.2 D5.1(C) D6.1(C) D7.1(C) D8.2 D9.1(C) D10.1(C) D11.1(C) J11.2 J12.2 R75.1 R133.1 T1.8,9(S) U16.2(GND) U21.2(GND) U29.2(-V) U31.1(-VIN)
GND_ISO: C150.2 U31.4(-VOUT)
+5V_LS: C22.1 U24.1(+VOUT)
+5V_U_HS: C100.1 U23.1(+VOUT)
+5V_V_HS: C113.1 U25.1(+VOUT)
+5V_W_HS: C119.1 U27.1(+VOUT)
+15V_LS: C21.1 U24.3(+VIN) ; off-sheet +15V_LS
+15V_U_HS: C93.1 U23.3(+VIN) ; off-sheet +15V_U_HS
+15V_V_HS: C107.1 U25.3(+VIN) ; off-sheet +15V_V_HS
+15V_W_HS: C115.1 U27.3(+VIN) ; off-sheet +15V_W_HS
DC+: C36.1 C151.1 C152.1 D13.2 D16.1 R143.2 T1.1(P1) ; off-sheet DC+
DC+_D: D13.1 D15.1(C)
DC-: C36.2 C46.2 C48.1 C53.1 C141.2 C143.2 C144.2 C148.2 C151.2 C152.2 J10.1 R71.1 R74.1 R81.1 R138.2 T1.5(P0) U30.15(GND) U30.20(GND) U30.EPAD ; off-sheet DC-
FLY+0: R142.2 R143.1
FLY+1: R141.2 R142.1
FLY_IN: D16.2 U30.1(VIN) U30.2(VIN) U30.3(VIN)
FLY_S: Q1.3(Power_Source) Q1.4(Power_Source) Q1.5(Power_Source) Q1.6(Power_Source) Q1.7(Power_Source) R81.2
S1: C93.2 C100.2 U23.2(GND) ; off-sheet S1
S3: C107.2 C113.2 U25.2(GND) ; off-sheet S3
S5: C115.2 C119.2 U27.2(GND) ; off-sheet S5
SL: C21.2 C22.2 U24.2(GND) ; off-sheet SL
XFMR3: D15.2(A) Q1.8(Drain) T1.3(P1*)
XFMR6: C145.1 D17.2 R72.2 T1.6(P0*)
NetC46_1: C46.1 R73.2 U30.9(BIAS)
NetC48_2: C48.2 R74.2 R139.2 R141.1 U30.17(EN/UVLO)
NetC133_1: C133.1 R133.2 R135.1 U29.3(+IN_A)
NetC141_1: C141.1 R137.1
NetC143_1: C143.1 J10.3 R139.1 U30.8(INTVCC)
NetC144_1: C144.1 R137.2 U30.13(VC)
NetC145_2: C145.2 R136.2
NetC148_1: C148.1 R140.1 U30.18(SENSE)
NetD5_2: D5.2(A) R103.1
NetD6_2: D6.2(A) R104.1
NetD7_2: D7.2(A) R112.1
NetD9_2: D9.2(A) R82.1 R83.1
NetD10_2: D10.2(A) R84.1 R85.1
NetD11_2: D11.2(A) R87.1 R88.1
NetD14_1,2: D14.1,2 T1.10,11(S*)
NetD17_1: D17.1 R73.1
NetJ10_2: J10.2 U30.16(SMODE)
NetQ1_1: Q1.1(Gate) R76.2
NetQ1_2: Q1.2(Driver_Source) R140.2
NetR69_1: R69.1 U30.11(TC)
NetR69_2: R69.2 R71.2 R72.1 U30.12(FB)
NetR76_1: R76.1 U30.19(GATE)
NetR136_1: R136.1 U30.10(DCM)
NetR138_1: R138.1 U30.14(IREG/SS)

Not connected (* = marked no-connect by the designer): T1 2(NC1) 4(NC0) 7(NC2) 12(NC3); U31 8(NC)

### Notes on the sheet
- (near J10) DIS
- EN
- SMODE disabled ("DIS") by default. Switch jumper to enable ("EN").

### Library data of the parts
C21 C93 C107 C115 = C1608X7R1H334K080AC: CAP CER 0.33UF 50V X7R 0603; Manufacturer: TDK; Dielectric Material: Ceramic; Tolerance: 10%; Value: 330nF
C22 C100 C113 C119 C129 C131 C133 C141 = CMP-2006-03057-2: as C16 on sheet 05 - Sense
C29 C51 = CMP-05428-000644-1: CAP ALUM POLY 470UF 20% 25V SMD; Manufacturer: PANASONIC; Manufacturer Part Number: EEH-ZK1E471P; ESR (Equivalent Series Resistance): 20mR; Life (Hours): 4000Hour; Value: 470μF
C36 = 890724427001CS: WCAP-FTDB DC-LINK CAPACITOR (MKP; Manufacturer: WURTH; Dissipation Factor @1kHz: 0.09%; Insulation Resistance: 10GΩ; Pitch: 27.5mm; Rate of Voltage Rise: 70V/µs; Technical Reference: MDBP275105J900DCPP15020; Value: 1µF
C43-C45 = CMP-08246-006112-1: CAP CER 33UF 25V JB 1206; Manufacturer: TDK; Tolerance: 20%; Dielectric Material: Ceramic; Value: 33μF
C46 = CMP-13271-004306-1: CAP CER 4.7UF 50V X5R 0805; Manufacturer: SAMSUNG; Tolerance: 10%; Value: 4.7μF
C48 C148 = CMP-2006-03341-2: CAP CER 1000PF 100V C0G/NP0 0603; Manufacturer: KEMET; Material: Ceramic; Value: 1nF; Automotive Grade: Grade 1; Temperature Coefficient: 30ppm/°C; Temperature Characteristic: C0G; Tolerance: 0.05
C53 = CMP-02417-000069-1: CAP CER 2200PF 760VAC Y5U RADIAL; Manufacturer: VISHAY; Lead Diameter: 0.6mm; Ratings: X1; Lead/Base Style: Kinked; Voltage: 500V; Tolerance: 20%; Value: 2.2nF
C120 C123 C146 C147 C149 C150 = CMP-13271-001434-1: CAP CER 10UF 25V X7R 1206; Manufacturer: SAMSUNG; Tolerance: 10%; Value: 10μF
C143 = CL10A475MA8NQNC: as C13 on sheet 05 - Sense
C144 C145 = CMP-2006-03416-2: CAP CER 47PF 100V 10% NP0 0603; Manufacturer: KEMET; Tolerance: 0.1; Temperature Coefficient: 30ppm/°C; Temperature Characteristic: C0G; Automotive Grade: Grade 1; Material: Ceramic
C151 C152 = CMP-08246-006150-1: CAP CER 10000PF 2KV X7S 2220; Manufacturer: TDK; Tolerance: 10%; Value: 10nF
D5-D7 = CMP-22017-000007-1: LED GREEN CLEAR CHIP SMD; Luminous Intensity: 12mcd; Lens Color: Colorless; Dominant Wavelength: 569nm; Number of LEDs: 1; Power Dissipation: 100mW; Viewing Angle: 130°; Reverse Voltage: 5V; Test Current: 10mA; Forward Voltage: 2.1V; Wavelength: 585nm; Lens Style: Diffused; Forward Current: 30mA
D8 = CMOZ13V TR PBFREE: DIODE ZENER 13V 300MW SOD523; Description: Diode Zener Single 13V 5% 350mW 2-Pin SOD-523 T/R; Tolerance: 5%; Impedance: 30R
D9-D11 = APTR3216-VFX: 3.2X1.6MM Purple SMD Led (X=0.19, Y=0.05), Rohs
D13 = SMBJ188A: TVS DIODE 188VWM DO214AA; Mfr_Name: Littelfuse Inc; Type: DEV; Peak Pulse Power: 600W; Clamping Voltage: 328V; Max Surge Current: 2A; Number of Channels: 1; Polarity: Unidirectional; Operating Supply Voltage: 188V; Breakdown Voltage: 209V; Power Line Protection: No; Diode Type: ZENER
D14 = FSV20120V: DIODE SCHOTTKY 120V 20A TO277-3; Element Configuration: Single; Max Forward Surge Current (Ifsm): 270A
D15 = US1MFA: DIODE GEN PURP 1KV 1A SOD123FA; Peak Reverse Current: 5uA; Max Surge Forward Current: 30A; Automotive Grade: Grade 0; Max Junction Temp: +150°C; Max Repetitive Reverse Voltage: 1000V; Capacitance: 15pF
D16 = BZG03C220-M3-08: DIODE ZENER 220V 1.25W DO214AC; Tolerance: 5.68%; Impedance: 750R
D17 = BAV20WS-7-F: DIODE GEN PURP 150V 200MA SOD323; Type: DEV; Reverse Recovery Time: 50ns; Max Repetitive Reverse Voltage (Vrrm): 200V; Element Configuration: Single; Max Reverse Current: 100nA; Forward Voltage: 1.25V; Peak Non-Repetitive Surge Current: 2.5A; Power Dissipation: 200mW; Polarity: Standard; Capacitance: 5pF
J10 = 61300311121: CONN HEADER VERT 3POS 2.54MM; Number of Positions: 3; Gender: Male; Connector Type: Male Pin; Pitch: 0.1inch
J11 J12 = CMP-2000-05417-1: CONN HEADER VERT 2POS 2.54MM; Standards: RoHSCompliant,ELVCompliant,UL94V-0; Material, Housing: Polyester; Agency Approvals: CSA,UL; Brand/Series: MTA-100Series; Contact Centerline Spacing: 0.100 / in.; Material, Contact: CopperAlloy; Current, Rating: 5 / A; Color, Housing: White; Contact Termination Area Plating: Tin; Special Features: Pinstrip; Number of Positions: 2; Pin Spacing: 0.1 / "; Temperature, Operating: -55to+105 / degC; Angle: Straight; Mount Angle: Vertical; Connector Type: MTA-100; Primary Type: InterconnectSystem; Voltage, Rating: 250 / V; Mounting Hole Size: 0.04 / "
Q1 = CMP-240936-000109-2: SICFET N-CH 900V 11A D2PAK-7; Max Power Dissipation: 50W; Input Capacitance: 150pF; Rds On Max: 360mR; Threshold Voltage: 2.1V
R69 = RT0603FRE07121KL: RES SMD 121K OHM 1% 1/10W 0603; Manufacturer: YAGEO; Temperature Coefficient: 50ppm/°C; Voltage Rating (DC): 50V; Voltage Rating: 75V; Max Power Dissipation: 100mW; Value: 121kΩ
R71 = RC0603FR-074K53L: RES 4.53K OHM 1% 1/10W 0603; Manufacturer: YAGEO; Temperature Coefficient: 100ppm/°C; Voltage Rating: 50V; Max Power Dissipation: 100mW; Value: 4.53kΩ
R72 = RT0603BRD0744K2L: RES SMD 44.2KOHM 0.1% 1/10W 0603; Manufacturer: YAGEO; Temperature Coefficient: 25ppm/°C; Power Rating: 100mW; Voltage Rating (DC): 50V; Voltage Rating: 75V; Value: 44.2kΩ
R73 = RC0603JR-0710RL: as R97 on sheet 05 - Sense
R74 = RC0603FR-135K6L: RES 5.6K OHM 1% 1/10W 0603; Manufacturer: YAGEO; Temperature Coefficient: 100ppm/°C; Voltage Rating: 50V; Value: 5.6kΩ
R75 = RT1206FRE072KL: RES SMD 2K OHM 1% 1/4W 1206; Manufacturer: YAGEO; Temperature Coefficient: 50ppm/°C; Power Rating: 250mW; Voltage Rating: 200V; Value: 2kΩ
R76 = RT0805FRE0720RL: RES SMD 20 OHM 1% 1/8W 0805; Manufacturer: YAGEO; Temperature Coefficient: 50ppm/°C; Power Rating: 125mW; Voltage Rating: 150V; Value: 20Ω
R81 = WFC1206R0500FE66: Res 0.05 Ohm 1.0 W 1% 1206 SMD; Manufacturer: VISHAY
R82-R85 R87 R88 = CRCW08051K00JNTA: RES SMD 1K OHM 5% 1/8W 0805; Manufacturer: VISHAY; Temperature Coefficient: 200ppm/°C; Max Power Dissipation: 125mW; Voltage Rating: 150V; Value: 1kΩ
R103 = RT0805FRE072KL: RES SMD 2K OHM 1% 1/8W 0805; Manufacturer: YAGEO; Temperature Coefficient: 50ppm/°C; Power Rating: 125mW; Voltage Rating (DC): 150V; Value: 2kΩ
R104 = RC0805FR-07499RL: RES 499 OHM 1% 1/8W 0805; Manufacturer: YAGEO; Power Rating: 125mW; Voltage Rating: 150V; Temperature Coefficient: 100ppm/°C; Value: 499Ω
R112 = RC0805FR-07249RL: RES 249 OHM 1% 1/8W 0805; Manufacturer: YAGEO; Voltage Rating: 150V; Max Power Dissipation: 125mW; Temperature Coefficient: 100ppm/°C; Value: 249Ω
R133 R135 = RT0603DRD071KL: RES SMD 1K OHM 0.5% 1/10W 0603; Manufacturer: YAGEO; Temperature Coefficient: 25ppm/°C; Max Power Dissipation: 100mW; Voltage Rating (DC): 50V; Voltage Rating: 75V; Value: 1kΩ
R136 R137 = ERJ3EKF1002V: RES SMD 10K OHM 1% 1/10W 0603; Manufacturer: PANASONIC; Manufacturer Part Number: ERJ-3EKF1002V; Temperature Coefficient: 100ppm/°C; Power Rating: 100mW; Voltage Rating: 75V; Value: 10kΩ
R138 = RT0603BRD0756K2L: RES SMD 56.2KOHM 0.1% 1/10W 0603; Manufacturer: YAGEO; Temperature Coefficient: 25ppm/°C; Max Power Dissipation: 100mW; Voltage Rating: 75V; Voltage Rating (DC): 50V; Value: 56.2kΩ
R139 = RC0603FR-070RL: as R52 on sheet 05 - Sense
R140 = RT0603FRE07100RL: RES SMD 100 OHM 1% 1/10W 0603; Manufacturer: YAGEO; Temperature Coefficient: 50ppm/°C; Voltage Rating: 75V; Max Power Dissipation: 100mW; Value: 100Ω
R141-R143 = RT1206DRD07499KL: RES SMD 499K OHM 0.5% 1/4W 1206; Manufacturer: YAGEO; Temperature Coefficient: 25ppm/°C; Voltage Rating (DC): 200V; Value: 499kΩ
T1 = 11328-T078: TRANSFORMER FLYBACK 670UH TH; Value: 670μH
U16 = R-78E5.0-1.0: DC DC CONVERTER 5V 5W; Number of Outputs: 1; Min Input Voltage: 8V; Max Input Voltage: 28V; Max Output Current: 1A; Efficiency: 91%
U21 = R-78E3.3-1.0: DC DC CONVERTER 3.3V 3W; Number of Outputs: 1; Min Input Voltage: 8V; Max Input Voltage: 28V; Max Output Current: 1A; Efficiency: 91%; Max Output Power: 3.3W; Min Input Voltage (DC): 7V
U23-U25 U27 = AS78L05RTR-G1: IC REG LINEAR 5V 100MA SOT89-3; Max Power Dissipation: 750mW; Dropout Voltage: 1.8V; Number of Outputs: 1; Max Input Voltage: 30V; Polarity: Positive; Quiescent Current: 3mA; Accuracy: 5%; Output Type: Fixed
U29 = CMP-0384-01498-2: IC OPAMP GP 1 CIRCUIT SOT23-5; Generic Part Number: AD8541; Slew Rate: 920mV/us; Input Bias Current: 4pA; V Span Max: 5.5V; Amplifiers Per Package: 1; Small Signal Bandwidth: 1MHz; Input Offset Voltage: 1mV; Iq/Amp: 65uA; V Span Min: 2.7V
U30 = LT8316EFE#PBF: 600VIN MICROPOWER, ISOLATED NO-O
U31 = CMP-29842-000014-1: DC DC CONVERTER 5V 1W; Min Input Voltage (DC): 4.5V; Max Input Voltage (DC): 5.5V; Output Current: 200mA; Isolation Voltage: 1kV; Efficiency: 75%; Number of Outputs: 1; Isolation: Isolated

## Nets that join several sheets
+1.65V: 05 - Sense (R62.2 R119.2 R131.2), 06 - Auxiliary Power (C129.1 U29.1 U29.4)
+3.3V: 02 - Power Stage (Q2.NTC1), 03 - Controller (6 pins), 04 - Gate Drivers (C111.1 U26.5), 05 - Sense (18 pins), 06 - Auxiliary Power (6 pins)
+5V: 03 - Controller (15 pins), 04 - Gate Drivers (20 pins), 06 - Auxiliary Power (5 pins)
+5V_ISO: 03 - Controller (C49.1 J13.9 U20.8), 06 - Auxiliary Power (C150.1 U31.5)
+12V: 02 - Power Stage (C121.1 D12.2 K1.3), 03 - Controller (TP8.1), 04 - Gate Drivers (L2.1 L3.1 L4.1 L5.1), 06 - Auxiliary Power (21 pins)
GND: 02 - Power Stage (6 pins), 03 - Controller (31 pins), 04 - Gate Drivers (52 pins), 05 - Sense (24 pins), 06 - Auxiliary Power (30 pins)
GND_ISO: 03 - Controller (5 pins), 06 - Auxiliary Power (C150.2 U31.4)
+5V_LS: 05 - Sense (C19.1 C109.1 U14.1), 06 - Auxiliary Power (C22.1 U24.1)
+5V_U_HS: 05 - Sense (C13.1 C16.1 U9.1), 06 - Auxiliary Power (C100.1 U23.1)
+5V_V_HS: 05 - Sense (C18.1 C23.1 U13.1), 06 - Auxiliary Power (C113.1 U25.1)
+5V_W_HS: 05 - Sense (C24.1 C28.1 U15.1), 06 - Auxiliary Power (C119.1 U27.1)
+15V_LS: 04 - Gate Drivers (8 pins), 06 - Auxiliary Power (C21.1 U24.3)
+15V_U_HS: 04 - Gate Drivers (C99.1 C101.1 U10.5 U12.7), 06 - Auxiliary Power (C93.1 U23.3)
+15V_V_HS: 04 - Gate Drivers (C89.1 C90.1 U7.5 U8.7), 06 - Auxiliary Power (C107.1 U25.3)
+15V_W_HS: 04 - Gate Drivers (C82.1 C83.1 U5.5 U6.7), 06 - Auxiliary Power (C115.1 U27.3)
CLK_I_U: 03 - Controller (U11.109), 05 - Sense (R36.2)
CLK_I_V: 03 - Controller (U11.105), 05 - Sense (R44.2)
CLK_I_W: 03 - Controller (U11.101), 05 - Sense (R48.2)
CLK_V_DC: 03 - Controller (U11.102), 05 - Sense (R50.2)
DAT_I_U: 03 - Controller (U11.107), 05 - Sense (R33.2)
DAT_I_V: 03 - Controller (U11.103), 05 - Sense (R41.2)
DAT_I_W: 03 - Controller (U11.99), 05 - Sense (R46.2)
DAT_V_DC: 03 - Controller (U11.100), 05 - Sense (R49.2)
DC+: 02 - Power Stage (17 pins), 05 - Sense (R86.2), 06 - Auxiliary Power (7 pins)
DC-: 02 - Power Stage (18 pins), 06 - Auxiliary Power (19 pins)
G1: 02 - Power Stage (J7.1 Q2.G1), 04 - Gate Drivers (R35.2 R40.2)
G2: 02 - Power Stage (J2.1 Q2.G2), 04 - Gate Drivers (R13.2 R16.2)
G3: 02 - Power Stage (J6.1 Q2.G3), 04 - Gate Drivers (R29.2 R32.2)
G4: 02 - Power Stage (J3.1 Q2.G4), 04 - Gate Drivers (R17.2 R20.2)
G5: 02 - Power Stage (J5.1 Q2.G5), 04 - Gate Drivers (R25.2 R28.2)
G6: 02 - Power Stage (J4.1 Q2.G6), 04 - Gate Drivers (R21.2 R23.2)
GD_DIS: 03 - Controller (U11.93), 04 - Gate Drivers (R59.1)
NTC: 02 - Power Stage (Q2.NTC2), 04 - Gate Drivers (C105.1 R95.1 R96.2)
NTC_MEAS: 03 - Controller (U11.30), 04 - Gate Drivers (C130.1 R134.2)
S1: 02 - Power Stage (J7.2,3,4,5 Q2.S1), 04 - Gate Drivers (5 pins), 05 - Sense (C13.2 C16.2 U9.4), 06 - Auxiliary Power (C93.2 C100.2 U23.2)
S3: 02 - Power Stage (J6.2,3,4,5 Q2.S3), 04 - Gate Drivers (5 pins), 05 - Sense (C18.2 C23.2 U13.4), 06 - Auxiliary Power (C107.2 C113.2 U25.2)
S5: 02 - Power Stage (J5.2,3,4,5 Q2.S5), 04 - Gate Drivers (5 pins), 05 - Sense (C24.2 C28.2 U15.4), 06 - Auxiliary Power (C115.2 C119.2 U27.2)
SL: 02 - Power Stage (6 pins), 04 - Gate Drivers (9 pins), 05 - Sense (6 pins), 06 - Auxiliary Power (C21.2 C22.2 U24.2)
U: 02 - Power Stage (Q2.U R89.1 TP5.1), 05 - Sense (R34.1)
U_HS_PWM: 03 - Controller (U11.49), 04 - Gate Drivers (U17.8)
U_LS_PWM: 03 - Controller (U11.51), 04 - Gate Drivers (U17.9)
U_MEAS: 03 - Controller (U11.17), 05 - Sense (C132.1 R67.2)
U_OUT: 02 - Power Stage (J9.4 R89.2), 05 - Sense (R38.1 R58.1)
V: 02 - Power Stage (Q2.V R43.1 TP6.1), 05 - Sense (R42.1)
V_HS_PWM: 03 - Controller (U11.53), 04 - Gate Drivers (U17.5)
V_LS_PWM: 03 - Controller (U11.55), 04 - Gate Drivers (U17.6)
V_MEAS: 03 - Controller (U11.11), 05 - Sense (C140.1 R68.2)
V_OUT: 02 - Power Stage (J9.3 R43.2), 05 - Sense (R45.1 R106.1)
W: 02 - Power Stage (Q2.W R99.1 TP7.1), 05 - Sense (R47.1)
W_HS_PWM: 03 - Controller (U11.50), 04 - Gate Drivers (U17.2)
W_LS_PWM: 03 - Controller (U11.52), 04 - Gate Drivers (U17.3)
W_MEAS: 03 - Controller (U11.9), 05 - Sense (C142.1 R70.2)
W_OUT: 02 - Power Stage (J9.2 R99.2), 05 - Sense (R51.1 R120.1)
